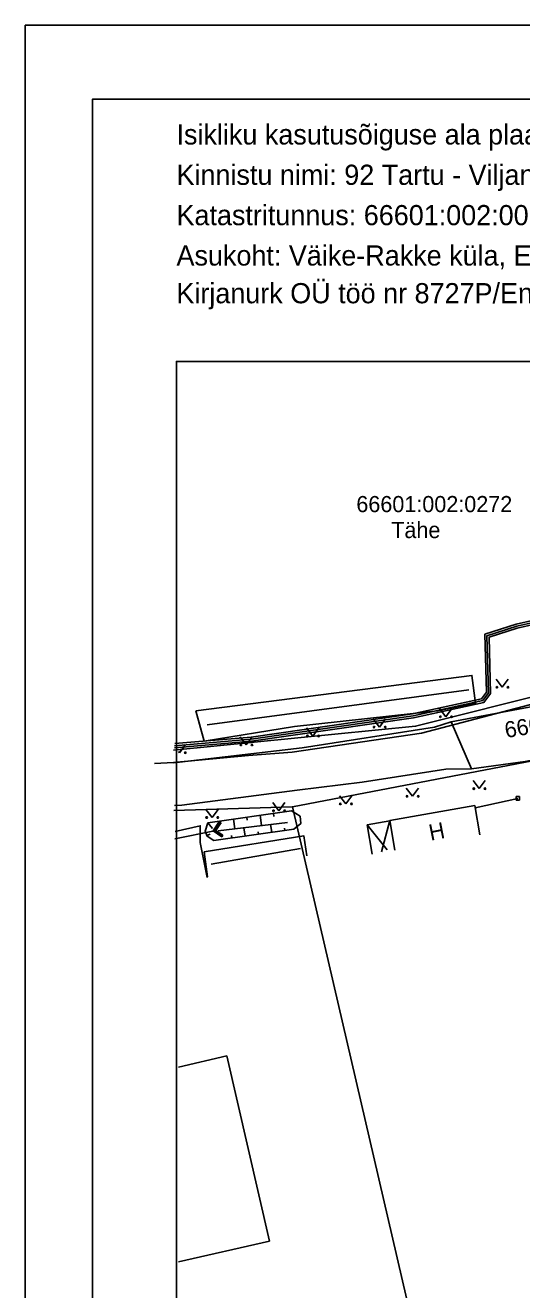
# Model space of a CAD drawing. Extents: x 627624 to 627729, y 6468528 to 6468676.
# Drawn here: x 627623.6 to 627660.6, y 6468582.3 to 6468676.3 of the extents above; entities that cross this region are included whole.
import ezdxf

# ---------------------------------------------------------------- set-up
doc = ezdxf.new("R2010")
doc.units = 0
for name, color, linetype in [('AED', 7, 'Continuous'), ('HALJASTUS', 7, 'Continuous'), ('HOONE', 7, 'Continuous'), ('Hoone Elu- või ühiskondlik hoone', 7, 'Continuous'), ('HOONEDET', 7, 'Continuous'), ('KPKAABEL', 7, 'Continuous'), ('MPKAABEL', 7, 'Continuous'), ('PIIR', 7, 'Continuous'), ('PR_SIDE', 7, 'Continuous'), ('RELJEEF', 7, 'Continuous'), ('TEE', 7, 'Continuous'), ('TRUUP', 7, 'Continuous'), ('VORMISTUS', 7, 'Continuous')]:
    doc.layers.add(name, color=color, linetype=linetype)

msp = doc.modelspace()

# ---------------------------------------------------------------- linework, layer by layer
at = {"layer": 'AED'}
for p, q in [((627660.291, 6468618.862), (627657.113, 6468618.168)), ((627660.166, 6468618.987), (627660.166, 6468618.737)), ((627660.166, 6468618.987), (627660.416, 6468618.987)), ((627660.166, 6468618.737), (627660.416, 6468618.737)), ((627660.416, 6468618.987), (627660.416, 6468618.737))]:
    msp.add_line(p, q, dxfattribs=at)
at = {"layer": 'HALJASTUS'}
for p, q in [((627658.671, 6468627.731), (627659.135, 6468627.125)), ((627659.135, 6468627.125), (627659.58, 6468627.731)), ((627637.187, 6468624.338), (627656.639, 6468626.929)), ((627654.473, 6468625.531), (627654.937, 6468624.925)), ((627654.937, 6468624.925), (627655.382, 6468625.531)), ((627649.535, 6468624.768), (627649.998, 6468624.161)), ((627649.998, 6468624.161), (627650.444, 6468624.768)), ((627639.623, 6468623.44), (627640.087, 6468622.834)), ((627640.087, 6468622.834), (627640.532, 6468623.44)), ((627644.579, 6468624.104), (627645.043, 6468623.497)), ((627645.043, 6468623.497), (627645.488, 6468624.104)), ((627635.048, 6468622.349), (627635.122, 6468622.252)), ((627635.122, 6468622.252), (627635.568, 6468622.859)), ((627651.992, 6468619.623), (627652.455, 6468619.016)), ((627652.455, 6468619.016), (627652.901, 6468619.623)), ((627656.96, 6468620.189), (627657.423, 6468619.582)), ((627657.423, 6468619.582), (627657.869, 6468620.189)), ((627647.024, 6468619.057), (627647.487, 6468618.45)), ((627647.487, 6468618.45), (627647.933, 6468619.057)), ((627637.075, 6468618.044), (627637.539, 6468617.437)), ((627637.539, 6468617.437), (627637.984, 6468618.044)), ((627642.05, 6468618.542), (627642.514, 6468617.935)), ((627642.514, 6468617.935), (627642.959, 6468618.542)), ((627637.463, 6468613.958), (627644.128, 6468615.143))]:
    msp.add_line(p, q, dxfattribs=at)
for points in [[(627636.336, 6468625.375), (627656.875, 6468628.003), (627657.149, 6468625.947), (627654.322, 6468625.361), (627643.674, 6468624.206), (627636.948, 6468623.11), (627636.336, 6468625.375)], [(627637.208, 6468613.025), (627636.953, 6468614.872), (627644.375, 6468616.069), (627644.586, 6468614.575)]]:
    msp.add_lwpolyline(points, dxfattribs=at)
for centre in [(627658.734, 6468627.125), (627659.562, 6468627.125), (627654.536, 6468624.925), (627655.364, 6468624.925), (627644.641, 6468623.497), (627645.47, 6468623.497), (627649.597, 6468624.161), (627650.426, 6468624.161), (627639.686, 6468622.834), (627640.515, 6468622.834), (627635.55, 6468622.252), (627657.022, 6468619.582), (627657.851, 6468619.582), (627652.054, 6468619.016), (627652.883, 6468619.016), (627642.113, 6468617.935), (627642.942, 6468617.935), (627647.086, 6468618.45), (627647.915, 6468618.45), (627637.138, 6468617.437), (627637.967, 6468617.437)]:
    msp.add_circle(centre, 0.055, dxfattribs=at)
at = {"layer": 'HOONE'}
for p, q in [((627650.758, 6468617.203), (627657.084, 6468618.331)), ((627657.474, 6468616.146), (627657.084, 6468618.331)), ((627649.076, 6468616.886), (627650.761, 6468617.186)), ((627649.466, 6468614.701), (627649.076, 6468616.886)), ((627651.147, 6468615.018), (627650.758, 6468617.203))]:
    msp.add_line(p, q, dxfattribs=at)
at = {"layer": 'Hoone Elu- või ühiskondlik hoone'}
msp.add_lwpolyline([(627635.048, 6468598.881), (627638.63, 6468599.711), (627641.81, 6468585.941), (627635.048, 6468584.397)], dxfattribs=at)
at = {"layer": 'HOONEDET'}
for p, q in [((627649.076, 6468616.886), (627650.564, 6468615.033)), ((627650.758, 6468617.203), (627650.14, 6468614.889))]:
    msp.add_line(p, q, dxfattribs=at)
at = {"layer": 'KPKAABEL'}
msp.add_lwpolyline([(627685.782, 6468640.643), (627682.599, 6468638.441), (627678.043, 6468635.809), (627672.046, 6468634.344), (627660.214, 6468631.662), (627657.997, 6468630.954), (627658.117, 6468626.708), (627657.689, 6468626.13), (627652.495, 6468625.008), (627640.455, 6468623.259), (627634.742, 6468622.776)], dxfattribs=at)
at = {"layer": 'MPKAABEL'}
for points in [[(627685.699, 6468640.768), (627682.519, 6468638.568), (627677.987, 6468635.95), (627672.012, 6468634.49), (627660.175, 6468631.807), (627657.844, 6468631.063), (627657.966, 6468626.756), (627657.602, 6468626.265), (627652.468, 6468625.156), (627640.438, 6468623.408), (627634.759, 6468622.928)], [(627634.732, 6468622.624), (627640.472, 6468623.11), (627652.522, 6468624.86), (627657.776, 6468625.995), (627658.268, 6468626.66), (627658.15, 6468630.845), (627660.253, 6468631.517), (627672.08, 6468634.198), (627673.058, 6468632.736)]]:
    msp.add_lwpolyline(points, dxfattribs=at)
at = {"layer": 'PIIR'}
for points in [[(627672.184, 6468651.3), (627686.69, 6468632.75), (627684.35, 6468632.16), (627652.69, 6468624.22), (627634.665, 6468622.433)], [(627634.665, 6468622.433), (627652.69, 6468624.22), (627684.35, 6468632.16), (627688.18, 6468626.77), (627643.52, 6468618.24), (627634.7, 6468617.952)], [(627660.121, 6468546.6), (627653, 6468577.43), (627643.52, 6468618.24), (627688.18, 6468626.77), (627717.444, 6468584.146)], [(627634.7, 6468617.952), (627643.52, 6468618.24), (627653, 6468577.43), (627660.121, 6468546.6)]]:
    msp.add_lwpolyline(points, dxfattribs=at)
at = {"layer": 'PR_SIDE'}
msp.add_lwpolyline([(627701.716, 6468585.772), (627703.748, 6468589.737), (627710.584, 6468595.905), (627710.644, 6468596.87), (627707.669, 6468601.201), (627693.442, 6468621.512), (627692.377, 6468622.22), (627689.672, 6468624.5), (627676.659, 6468629.413), (627665.71, 6468626.997), (627653.138, 6468623.704), (627643.511, 6468622.305), (627640.257, 6468622.059), (627634.674, 6468621.524), (627633.255, 6468621.458)], dxfattribs=at)
at = {"layer": 'RELJEEF'}
for p, q in [((627642.109, 6468617.75), (627642.143, 6468617.512)), ((627637.236, 6468617.048), (627637.572, 6468616.61)), ((627638.15, 6468617.18), (627638.181, 6468616.969)), ((627639.14, 6468617.322), (627639.244, 6468616.596)), ((627640.13, 6468617.465), (627640.162, 6468617.24)), ((627641.12, 6468617.607), (627641.23, 6468616.838)), ((627641.976, 6468616.335), (627641.894, 6468616.919)), ((627637.149, 6468616.105), (627637.407, 6468616.207)), ((627639.005, 6468615.919), (627638.978, 6468616.11)), ((627639.995, 6468616.058), (627639.908, 6468616.677)), ((627640.985, 6468616.196), (627640.96, 6468616.377)), ((627642.966, 6468616.474), (627642.942, 6468616.644))]:
    msp.add_line(p, q, dxfattribs=at)
for points in [[(627637.236, 6468617.048), (627637.028, 6468616.411), (627637.175, 6468616.04), (627637.673, 6468615.732), (627643.614, 6468616.565), (627644.14, 6468616.982), (627644.103, 6468617.529), (627643.444, 6468617.942), (627637.236, 6468617.048)], [(627637.992, 6468616.444), (627643.159, 6468617.072)]]:
    msp.add_lwpolyline(points, dxfattribs=at)
at = {"layer": 'TEE'}
for points in [[(627691.556, 6468636.216), (627691.411, 6468633.572), (627690.377, 6468632.362), (627688.302, 6468631.311), (627683.705, 6468630.285), (627675.534, 6468628.326), (627664.963, 6468626.349), (627655.323, 6468624.553), (627656.855, 6468621.064), (627660.849, 6468621.603), (627663.795, 6468622.181), (627671.677, 6468623.939), (627678.512, 6468625.342), (627686.437, 6468627.071), (627694.212, 6468628.779), (627696.498, 6468628.635), (627697.947, 6468628.287), (627705.762, 6468618.126), (627714.785, 6468606.184), (627717.167, 6468602.8)], [(627655.323, 6468624.553), (627654.099, 6468624.153), (627644.239, 6468622.621), (627634.69, 6468621.493)], [(627634.747, 6468618.323), (627635.301, 6468618.359), (627643.867, 6468619.473), (627648.701, 6468620.075), (627654.943, 6468621.043), (627656.855, 6468621.064)], [(627634.788, 6468616.397), (627636.656, 6468616.822), (627636.646, 6468615.589), (627637.175, 6468612.988)]]:
    msp.add_lwpolyline(points, dxfattribs=at)
at = {"layer": 'TRUUP'}
for p, q in [((627638.054, 6468617.082), (627637.622, 6468616.435)), ((627637.989, 6468616.728), (627637.713, 6468616.571)), ((627638.113, 6468617.043), (627637.721, 6468616.454)), ((627638.019, 6468616.774), (627637.744, 6468616.618)), ((627638.05, 6468616.82), (627637.775, 6468616.664)), ((627638.081, 6468616.866), (627637.806, 6468616.71)), ((627638.172, 6468617.003), (627637.82, 6468616.474)), ((627638.112, 6468616.913), (627637.837, 6468616.756)), ((627638.143, 6468616.959), (627637.868, 6468616.803)), ((627638.171, 6468617.004), (627637.898, 6468616.849)), ((627638.148, 6468617.019), (627637.929, 6468616.895)), ((627638.125, 6468617.035), (627637.96, 6468616.941)), ((627638.102, 6468617.05), (627637.991, 6468616.988)), ((627638.078, 6468617.066), (627638.022, 6468617.034)), ((627638.172, 6468617.003), (627638.054, 6468617.082)), ((627637.721, 6468616.454), (627634.764, 6468615.862)), ((627637.622, 6468616.435), (627638.27, 6468616.003)), ((627637.896, 6468616.589), (627637.623, 6468616.434)), ((627637.865, 6468616.543), (627637.647, 6468616.418)), ((627637.927, 6468616.635), (627637.652, 6468616.479)), ((627637.835, 6468616.496), (627637.67, 6468616.403)), ((627637.958, 6468616.681), (627637.683, 6468616.525)), ((627637.832, 6468616.466), (627637.693, 6468616.387)), ((627637.855, 6468616.451), (627637.716, 6468616.372)), ((627637.721, 6468616.454), (627638.309, 6468616.062)), ((627637.878, 6468616.435), (627637.74, 6468616.356)), ((627637.902, 6468616.42), (627637.763, 6468616.341)), ((627637.925, 6468616.404), (627637.786, 6468616.325)), ((627637.948, 6468616.389), (627637.81, 6468616.31)), ((627637.82, 6468616.474), (627638.349, 6468616.122)), ((627637.972, 6468616.373), (627637.833, 6468616.294)), ((627637.995, 6468616.357), (627637.856, 6468616.279)), ((627638.018, 6468616.342), (627637.879, 6468616.263)), ((627638.041, 6468616.326), (627637.903, 6468616.248)), ((627638.065, 6468616.311), (627637.926, 6468616.232)), ((627638.088, 6468616.295), (627637.949, 6468616.217)), ((627638.111, 6468616.28), (627637.973, 6468616.201)), ((627638.135, 6468616.264), (627637.996, 6468616.186)), ((627638.158, 6468616.249), (627638.019, 6468616.17)), ((627638.181, 6468616.233), (627638.043, 6468616.155)), ((627638.205, 6468616.218), (627638.066, 6468616.139)), ((627638.228, 6468616.202), (627638.089, 6468616.124)), ((627638.251, 6468616.187), (627638.112, 6468616.108)), ((627638.274, 6468616.171), (627638.136, 6468616.092)), ((627638.298, 6468616.156), (627638.159, 6468616.077)), ((627638.321, 6468616.14), (627638.182, 6468616.061)), ((627638.344, 6468616.125), (627638.206, 6468616.046)), ((627638.324, 6468616.084), (627638.229, 6468616.03)), ((627638.293, 6468616.038), (627638.252, 6468616.015)), ((627638.349, 6468616.122), (627638.27, 6468616.003))]:
    msp.add_line(p, q, dxfattribs=at)
at = {"layer": 'VORMISTUS'}
for points in [[(627623.638, 6468676.344), (627728.638, 6468676.344), (627728.638, 6468527.844), (627623.638, 6468527.844)], [(627628.638, 6468533.344), (627723.638, 6468533.344), (627723.638, 6468670.844), (627628.638, 6468670.844)], [(627628.638, 6468670.844), (627723.638, 6468670.844), (627723.638, 6468533.344), (627628.638, 6468533.344)], [(627717.388, 6468546.344), (627634.888, 6468546.344), (627634.888, 6468651.344), (627717.388, 6468651.344)]]:
    msp.add_lwpolyline(points, close=True, dxfattribs=at)

# ---------------------------------------------------------------- texts
at = {"layer": 'HOONE'}
msp.add_text('H', height=1.2, rotation=11.20898, dxfattribs=at).set_placement((627653.807, 6468615.706))
at = {"layer": 'PIIR'}
for s, p in [('66601:002:0272', (627648.278, 6468640.142)), ('Tähe', (627650.876, 6468638.212))]:
    msp.add_text(s, height=1.2, dxfattribs=at).set_placement(p)
msp.add_text('66601:001:0245', height=1.2, rotation=9.56292, dxfattribs=at).set_placement((627659.419, 6468623.341))
at = {"layer": 'VORMISTUS'}
for s, p in [('Isikliku kasutusõiguse ala plaan', (627634.893, 6468667.478)), ('Kinnistu nimi: 92 Tartu - Viljandi - Kilingi-Nõmme tee (KV67639)', (627634.893, 6468664.478)), ('Katastritunnus: 66601:002:0012', (627634.893, 6468661.478))]:
    msp.add_text(s, height=1.5, dxfattribs=at).set_placement(p)
for s, p in [('Asukoht: Väike-Rakke küla, Elva vald, Tartu maakond', (627634.893, 6468658.478)), ('Kirjanurk OÜ töö nr 8727P/Enefit Connect OÜ tellimus VT1662', (627634.886, 6468655.673))]:
    msp.add_text(s, height=1.5, rotation=360, dxfattribs=at).set_placement(p)

doc.saveas('drawing.dxf')
